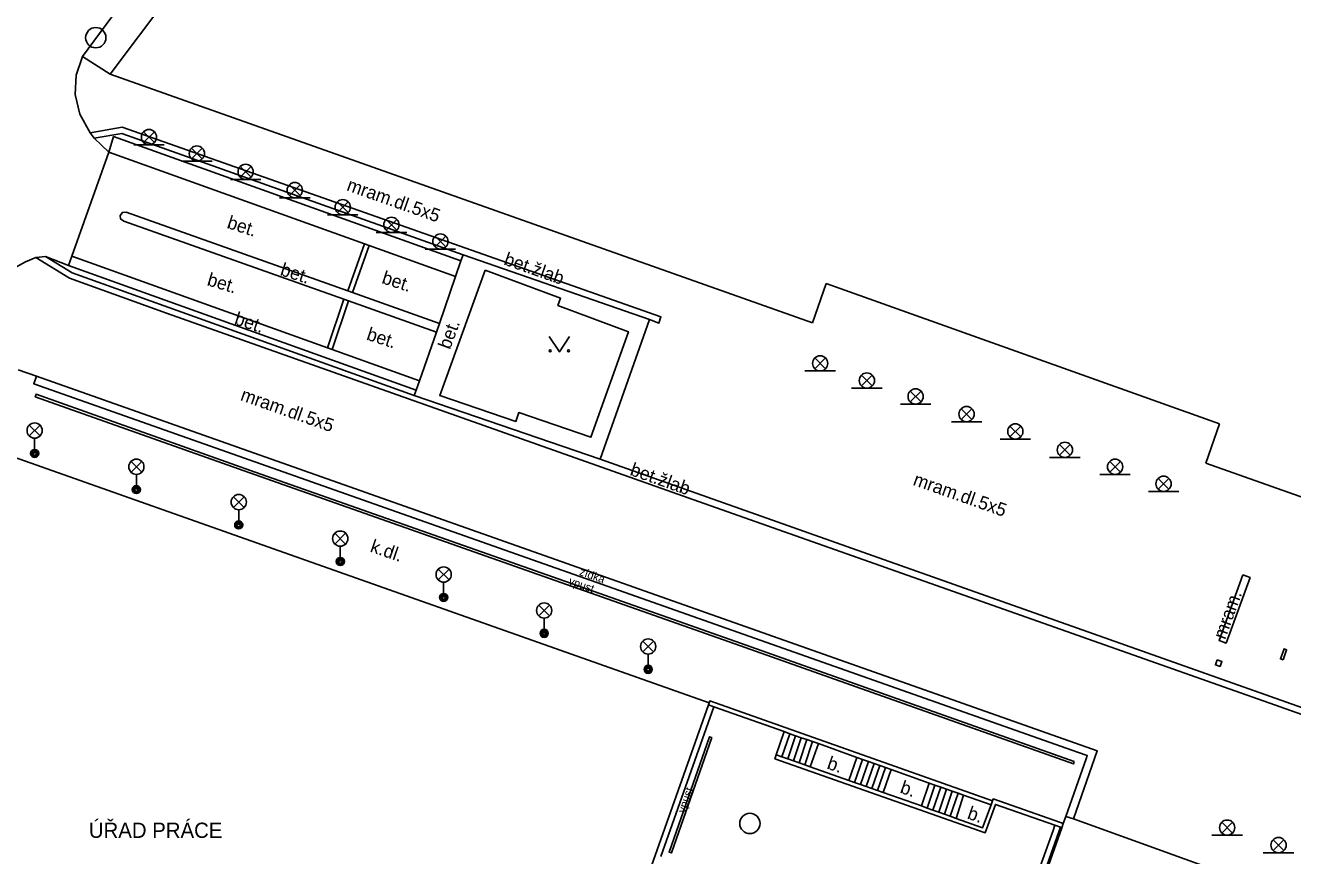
# Model space of a CAD drawing. Extents: x -598932 to -598196, y -1162207 to -1161504.
# Drawn here: x -598721.9 to -598659.5, y -1162142.2 to -1162101.4 of the extents above; entities that cross this region are included whole.
import ezdxf

# ---------------------------------------------------------------- set-up
doc = ezdxf.new("R2010")
doc.units = 0
for name, color, linetype in [('kanalizace - povrch.  znaky - skut. velikost', 7, 'Continuous'), ('Level 27', 7, 'Continuous'), ('Level 33', 7, 'Continuous'), ('Level 36', 7, 'Continuous'), ('TM - budovy zdene_ betonove - VP', 7, 'Continuous'), ('TM - chodniky - VP', 7, 'Continuous'), ('TM - horni hrana svahu', 7, 'Continuous'), ('TM - komunikace - VP', 7, 'Continuous'), ('TM - plot dreveny_ kovovy - VP', 7, 'Continuous'), ('TM - popis objektu', 7, 'Continuous'), ('TM - popis povrchu', 7, 'Continuous'), ('TM - poznamka', 7, 'Continuous'), ('TM - rozhrani ploch obecne - VP', 7, 'Continuous'), ('TM - schody - VP', 7, 'Continuous')]:
    doc.layers.add(name, color=color, linetype=linetype)

msp = doc.modelspace()

# ---------------------------------------------------------------- linework, layer by layer
at = {"layer": 'kanalizace - povrch.  znaky - skut. velikost'}
for points in [[(-598670.3, -1162137.6), (-598670.34, -1162137.72), (-598687.29, -1162131.71), (-598710.67, -1162123.47), (-598721.46, -1162119.64), (-598721.42, -1162119.52), (-598710.63, -1162123.35), (-598695.38, -1162128.72), (-598687.25, -1162131.59), (-598670.3, -1162137.6)], [(-598688.14, -1162136.42), (-598690.13, -1162142.1), (-598690.25, -1162142.06), (-598688.26, -1162136.38), (-598688.14, -1162136.42)]]:
    msp.add_lwpolyline(points, dxfattribs=at)
at = {"layer": 'Level 27'}
for centre in [(-598718.48, -1162101.96), (-598686.27, -1162140.65)]:
    msp.add_circle(centre, 0.5, dxfattribs=at)
at = {"layer": 'Level 33'}
for p, q in [((-598716.125, -1162107.12), (-598715.595, -1162106.59)), ((-598716.125, -1162106.59), (-598715.595, -1162107.12)), ((-598716.61, -1162107.23), (-598715.11, -1162107.23)), ((-598713.765, -1162107.93), (-598713.235, -1162107.4)), ((-598713.765, -1162107.4), (-598713.235, -1162107.93)), ((-598714.25, -1162108.04), (-598712.75, -1162108.04)), ((-598711.365, -1162108.83), (-598710.835, -1162108.3)), ((-598711.365, -1162108.3), (-598710.835, -1162108.83)), ((-598711.85, -1162108.94), (-598710.35, -1162108.94)), ((-598708.945, -1162109.73), (-598708.415, -1162109.2)), ((-598708.945, -1162109.2), (-598708.415, -1162109.73)), ((-598709.43, -1162109.84), (-598707.93, -1162109.84)), ((-598706.585, -1162110.57), (-598706.055, -1162110.04)), ((-598706.585, -1162110.04), (-598706.055, -1162110.57)), ((-598707.07, -1162110.68), (-598705.57, -1162110.68)), ((-598704.185, -1162111.44), (-598703.655, -1162110.91)), ((-598704.185, -1162110.91), (-598703.655, -1162111.44)), ((-598704.67, -1162111.55), (-598703.17, -1162111.55)), ((-598701.775, -1162112.26), (-598701.245, -1162111.73)), ((-598701.775, -1162111.73), (-598701.245, -1162112.26)), ((-598702.26, -1162112.37), (-598700.76, -1162112.37)), ((-598683.075, -1162118.26), (-598682.545, -1162117.73)), ((-598683.075, -1162117.73), (-598682.545, -1162118.26)), ((-598683.56, -1162118.37), (-598682.06, -1162118.37)), ((-598680.775, -1162119.11), (-598680.245, -1162118.58)), ((-598680.775, -1162118.58), (-598680.245, -1162119.11)), ((-598681.26, -1162119.22), (-598679.76, -1162119.22)), ((-598678.375, -1162119.89), (-598677.845, -1162119.36)), ((-598678.375, -1162119.36), (-598677.845, -1162119.89)), ((-598678.86, -1162120), (-598677.36, -1162120)), ((-598675.865, -1162120.76), (-598675.335, -1162120.23)), ((-598675.865, -1162120.23), (-598675.335, -1162120.76)), ((-598721.755, -1162121.57), (-598721.225, -1162121.04)), ((-598721.755, -1162121.04), (-598721.225, -1162121.57)), ((-598676.35, -1162120.87), (-598674.85, -1162120.87)), ((-598673.465, -1162121.61), (-598672.935, -1162121.08)), ((-598673.465, -1162121.08), (-598672.935, -1162121.61)), ((-598721.49, -1162121.68), (-598721.49, -1162122.43)), ((-598673.95, -1162121.72), (-598672.45, -1162121.72)), ((-598671.025, -1162122.52), (-598670.495, -1162121.99)), ((-598671.025, -1162121.99), (-598670.495, -1162122.52)), ((-598716.745, -1162123.35), (-598716.215, -1162122.82)), ((-598716.745, -1162122.82), (-598716.215, -1162123.35)), ((-598671.51, -1162122.63), (-598670.01, -1162122.63)), ((-598668.555, -1162123.35), (-598668.025, -1162122.82)), ((-598668.555, -1162122.82), (-598668.025, -1162123.35)), ((-598716.48, -1162123.46), (-598716.48, -1162124.21)), ((-598669.04, -1162123.46), (-598667.54, -1162123.46)), ((-598666.165, -1162124.19), (-598665.635, -1162123.66)), ((-598666.165, -1162123.66), (-598665.635, -1162124.19)), ((-598711.705, -1162125.09), (-598711.175, -1162124.56)), ((-598711.705, -1162124.56), (-598711.175, -1162125.09)), ((-598666.65, -1162124.3), (-598665.15, -1162124.3)), ((-598711.44, -1162125.2), (-598711.44, -1162125.95)), ((-598706.705, -1162126.89), (-598706.175, -1162126.36)), ((-598706.705, -1162126.36), (-598706.175, -1162126.89)), ((-598706.44, -1162127), (-598706.44, -1162127.75)), ((-598701.615, -1162128.66), (-598701.085, -1162128.13)), ((-598701.615, -1162128.13), (-598701.085, -1162128.66)), ((-598701.35, -1162128.77), (-598701.35, -1162129.52)), ((-598696.665, -1162130.43), (-598696.135, -1162129.9)), ((-598696.665, -1162129.9), (-598696.135, -1162130.43)), ((-598696.4, -1162130.54), (-598696.4, -1162131.29)), ((-598691.545, -1162132.2), (-598691.015, -1162131.67)), ((-598691.545, -1162131.67), (-598691.015, -1162132.2)), ((-598691.28, -1162132.31), (-598691.28, -1162133.06)), ((-598663.035, -1162141.12), (-598662.505, -1162140.59)), ((-598663.035, -1162140.59), (-598662.505, -1162141.12)), ((-598663.52, -1162141.23), (-598662.02, -1162141.23)), ((-598660.505, -1162141.98), (-598659.975, -1162141.45)), ((-598660.505, -1162141.45), (-598659.975, -1162141.98)), ((-598660.99, -1162142.09), (-598659.49, -1162142.09))]:
    msp.add_line(p, q, dxfattribs=at)
for centre, radius in [((-598715.86, -1162106.855), 0.375), ((-598713.5, -1162107.665), 0.375), ((-598711.1, -1162108.565), 0.375), ((-598708.68, -1162109.465), 0.375), ((-598706.32, -1162110.305), 0.375), ((-598703.92, -1162111.175), 0.375), ((-598701.51, -1162111.995), 0.375), ((-598682.81, -1162117.995), 0.375), ((-598680.51, -1162118.845), 0.375), ((-598678.11, -1162119.625), 0.375), ((-598675.6, -1162120.495), 0.375), ((-598721.49, -1162121.305), 0.375), ((-598673.2, -1162121.345), 0.375), ((-598721.49, -1162122.43), 0.2), ((-598721.49, -1162122.43), 0.145), ((-598721.49, -1162122.43), 0.0876), ((-598670.76, -1162122.255), 0.375), ((-598716.48, -1162123.085), 0.375), ((-598668.29, -1162123.085), 0.375), ((-598665.9, -1162123.925), 0.375), ((-598716.48, -1162124.21), 0.2), ((-598716.48, -1162124.21), 0.145), ((-598716.48, -1162124.21), 0.0876), ((-598711.44, -1162124.825), 0.375), ((-598711.44, -1162125.95), 0.2), ((-598711.44, -1162125.95), 0.145), ((-598711.44, -1162125.95), 0.0876), ((-598706.44, -1162126.625), 0.375), ((-598706.44, -1162127.75), 0.2), ((-598706.44, -1162127.75), 0.145), ((-598706.44, -1162127.75), 0.0876), ((-598701.35, -1162128.395), 0.375), ((-598701.35, -1162129.52), 0.2), ((-598701.35, -1162129.52), 0.145), ((-598701.35, -1162129.52), 0.0876), ((-598696.4, -1162130.165), 0.375), ((-598696.4, -1162131.29), 0.2), ((-598696.4, -1162131.29), 0.145), ((-598696.4, -1162131.29), 0.0876), ((-598691.28, -1162131.935), 0.375), ((-598691.28, -1162133.06), 0.2), ((-598691.28, -1162133.06), 0.145), ((-598691.28, -1162133.06), 0.0876), ((-598662.77, -1162140.855), 0.375), ((-598660.24, -1162141.715), 0.375)]:
    msp.add_circle(centre, radius, dxfattribs=at)
at = {"layer": 'Level 36'}
msp.add_lwpolyline([(-598696.15, -1162116.68), (-598695.65, -1162117.43), (-598695.15, -1162116.68)], dxfattribs=at)
for centre in [(-598696.1, -1162117.38), (-598695.201, -1162117.38)]:
    msp.add_circle(centre, 0.05, dxfattribs=at)
at = {"layer": 'TM - budovy zdene_ betonove - VP'}
for points in [[(-598710.79, -1162094.46), (-598717.77, -1162103.75)], [(-598717.77, -1162103.75), (-598683.19, -1162116)], [(-598683.19, -1162116), (-598682.51, -1162114.07)], [(-598682.51, -1162114.07), (-598663.14, -1162120.98)], [(-598663.14, -1162120.98), (-598663.82, -1162122.91)], [(-598688.27, -1162134.71), (-598724.7, -1162121.85)], [(-598663.82, -1162122.91), (-598634.85, -1162133.15)], [(-598728.07, -1162159.58), (-598700.55, -1162169.39), (-598688.31, -1162134.81)], [(-598670.71, -1162140.3), (-598670.84, -1162140.66)], [(-598670.34, -1162140.43), (-598670.71, -1162140.3)], [(-598642.61, -1162150.43), (-598670.34, -1162140.43)], [(-598670.91, -1162140.86), (-598682.79, -1162174.42)], [(-598670.84, -1162140.66), (-598670.91, -1162140.86)]]:
    msp.add_lwpolyline(points, dxfattribs=at)
at = {"layer": 'TM - chodniky - VP'}
for points in [[(-598722.3, -1162118.31), (-598721.4, -1162118.63)], [(-598721.4, -1162118.63), (-598669.17, -1162137.07), (-598670.34, -1162140.43)], [(-598660.02, -1162132.6), (-598660.15, -1162132.55), (-598659.97, -1162132.05), (-598659.84, -1162132.1), (-598660.02, -1162132.6)], [(-598663.27, -1162132.6), (-598663.03, -1162132.68), (-598663.12, -1162132.92), (-598663.35, -1162132.84), (-598663.27, -1162132.6)]]:
    msp.add_lwpolyline(points, dxfattribs=at)
at = {"layer": 'TM - horni hrana svahu'}
for points in [[(-598705.253, -1162112.11), (-598706.07, -1162114.43)], [(-598705.84, -1162114.51), (-598705.012, -1162112.196)], [(-598706.27, -1162114.84), (-598707.07, -1162117.23)], [(-598706.84, -1162117.31), (-598706.03, -1162114.92)]]:
    msp.add_lwpolyline(points, dxfattribs=at)
at = {"layer": 'TM - komunikace - VP'}
for points in [[(-598719.14, -1162102.89), (-598713.12, -1162094.74)], [(-598718.76, -1162106.64), (-598719.27, -1162105.73), (-598719.5, -1162104.75), (-598719.44, -1162103.8), (-598719.14, -1162102.89)], [(-598718.56, -1162106.91), (-598718.76, -1162106.64)], [(-598717.84, -1162107.6), (-598718.56, -1162106.91)], [(-598700.76, -1162113.72), (-598705.012, -1162112.196), (-598705.253, -1162112.11), (-598717.84, -1162107.6)], [(-598728.84, -1162119.71), (-598728.62, -1162119.43), (-598725.8, -1162115.62), (-598724.61, -1162114.53), (-598723.29, -1162113.73), (-598721.94, -1162112.99), (-598721.43, -1162112.79)], [(-598721.43, -1162112.79), (-598720.95, -1162112.73)], [(-598720.95, -1162112.73), (-598719.82, -1162113.18)], [(-598719.82, -1162113.18), (-598702.7, -1162119.32)], [(-598701.56, -1162116.03), (-598700.76, -1162113.72)], [(-598701.71, -1162116.46), (-598701.56, -1162116.03)], [(-598702.54, -1162118.85), (-598701.71, -1162116.46)], [(-598702.7, -1162119.32), (-598702.54, -1162118.85)], [(-598688.05, -1162134.9), (-598690.66, -1162142.27)], [(-598684.98, -1162137.27), (-598684.59, -1162136.13)], [(-598671.25, -1162140.73), (-598674.18, -1162139.71), (-598674.69, -1162141.11), (-598685.04, -1162137.46), (-598684.98, -1162137.27)], [(-598673.51, -1162147.01), (-598671.34, -1162140.99), (-598671.25, -1162140.73)]]:
    msp.add_lwpolyline(points, dxfattribs=at)
at = {"layer": 'TM - plot dreveny_ kovovy - VP'}
for points in [[(-598688.31, -1162134.81), (-598688.05, -1162134.9)], [(-598688.05, -1162134.9), (-598684.59, -1162136.13)]]:
    msp.add_lwpolyline(points, dxfattribs=at)
at = {"layer": 'TM - rozhrani ploch obecne - VP'}
for points in [[(-598719.14, -1162102.89), (-598717.77, -1162103.75)], [(-598718.76, -1162106.64), (-598717.18, -1162106.36), (-598690.65, -1162115.71), (-598690.75, -1162116.01), (-598691.21, -1162115.83)], [(-598700.39, -1162112.65), (-598717.19, -1162106.67), (-598718.56, -1162106.91)], [(-598717.84, -1162107.6), (-598717.6, -1162106.83), (-598700.5, -1162112.94)], [(-598717.84, -1162107.6), (-598719.66, -1162112.72)], [(-598706.27, -1162114.84), (-598717.1, -1162110.99), (-598717.26, -1162110.88), (-598717.28, -1162110.71), (-598717.17, -1162110.56), (-598716.98, -1162110.55), (-598706.07, -1162114.43)], [(-598721.43, -1162112.79), (-598719.78, -1162113.8), (-598714.99, -1162115.52), (-598689.31, -1162124.62), (-598650.44, -1162138.33), (-598639.68, -1162142.2)], [(-598720.95, -1162112.73), (-598719.65, -1162113.53), (-598702.8, -1162119.57)], [(-598719.66, -1162112.72), (-598719.82, -1162113.18)], [(-598719.66, -1162112.72), (-598707.07, -1162117.23)], [(-598700.76, -1162113.72), (-598700.5, -1162112.94)], [(-598700.5, -1162112.94), (-598700.39, -1162112.65)], [(-598691.21, -1162115.83), (-598700.39, -1162112.65)], [(-598699.3, -1162113.4), (-598695.59, -1162114.79), (-598695.72, -1162115.14), (-598692.25, -1162116.44), (-598694.1, -1162121.63), (-598697.65, -1162120.42), (-598697.79, -1162120.85), (-598701.54, -1162119.57), (-598699.3, -1162113.4)], [(-598706.03, -1162114.92), (-598706.27, -1162114.84)], [(-598706.07, -1162114.43), (-598705.84, -1162114.51), (-598701.56, -1162116.03)], [(-598701.71, -1162116.46), (-598706.03, -1162114.92)], [(-598691.21, -1162115.83), (-598693.65, -1162122.72)], [(-598707.07, -1162117.23), (-598706.84, -1162117.31), (-598702.54, -1162118.85)], [(-598670.71, -1162140.3), (-598669.72, -1162137.47), (-598669.66, -1162137.31), (-598670.09, -1162137.16), (-598721.53, -1162119), (-598721.4, -1162118.63)], [(-598702.7, -1162119.32), (-598702.8, -1162119.57)], [(-598702.8, -1162119.57), (-598693.65, -1162122.72)], [(-598693.65, -1162122.72), (-598650.35, -1162138.05)], [(-598661.99, -1162128.41), (-598661.64, -1162128.54), (-598662.82, -1162131.77), (-598663.17, -1162131.64), (-598661.99, -1162128.41)], [(-598688.31, -1162134.81), (-598688.27, -1162134.71)], [(-598688.27, -1162134.71), (-598688.24, -1162134.62), (-598674.33, -1162139.54)], [(-598684.3, -1162136.23), (-598684.59, -1162136.13)], [(-598684.02, -1162136.33), (-598684.3, -1162136.23)], [(-598683.74, -1162136.43), (-598684.02, -1162136.33)], [(-598683.46, -1162136.52), (-598683.74, -1162136.43)], [(-598683.18, -1162136.62), (-598683.46, -1162136.52)], [(-598682.89, -1162136.72), (-598683.3, -1162137.86)], [(-598682.89, -1162136.72), (-598683.18, -1162136.62)], [(-598681, -1162137.4), (-598682.89, -1162136.72)], [(-598684.69, -1162137.37), (-598684.98, -1162137.27)], [(-598684.41, -1162137.47), (-598684.69, -1162137.37)], [(-598684.13, -1162137.57), (-598684.41, -1162137.47)], [(-598683.85, -1162137.67), (-598684.13, -1162137.57)], [(-598683.57, -1162137.77), (-598683.85, -1162137.67)], [(-598683.3, -1162137.86), (-598683.57, -1162137.77)], [(-598681.4, -1162138.53), (-598683.3, -1162137.86)], [(-598681, -1162137.4), (-598681.4, -1162138.53)], [(-598680.72, -1162137.5), (-598681, -1162137.4)], [(-598680.43, -1162137.6), (-598680.72, -1162137.5)], [(-598680.15, -1162137.7), (-598680.43, -1162137.6)], [(-598679.87, -1162137.8), (-598680.15, -1162137.7)], [(-598679.59, -1162137.89), (-598679.87, -1162137.8)], [(-598679.31, -1162137.99), (-598679.59, -1162137.89)], [(-598681.12, -1162138.63), (-598681.4, -1162138.53)], [(-598679.31, -1162137.99), (-598679.71, -1162139.13)], [(-598677.44, -1162138.66), (-598679.31, -1162137.99)], [(-598680.83, -1162138.73), (-598681.12, -1162138.63)], [(-598680.55, -1162138.83), (-598680.83, -1162138.73)], [(-598680.27, -1162138.93), (-598680.55, -1162138.83)], [(-598679.99, -1162139.03), (-598680.27, -1162138.93)], [(-598679.71, -1162139.13), (-598679.99, -1162139.03)], [(-598677.82, -1162139.79), (-598679.71, -1162139.13)], [(-598677.44, -1162138.66), (-598677.82, -1162139.79)], [(-598677.16, -1162138.76), (-598677.44, -1162138.66)], [(-598676.87, -1162138.86), (-598677.16, -1162138.76)], [(-598676.59, -1162138.96), (-598676.87, -1162138.86)], [(-598676.31, -1162139.06), (-598676.59, -1162138.96)], [(-598676.02, -1162139.16), (-598676.31, -1162139.06)], [(-598675.75, -1162139.25), (-598676.02, -1162139.16)], [(-598677.54, -1162139.89), (-598677.82, -1162139.79)], [(-598675.75, -1162139.25), (-598676.12, -1162140.4)], [(-598674.39, -1162139.73), (-598674.81, -1162140.86), (-598676.12, -1162140.4)], [(-598674.39, -1162139.73), (-598675.75, -1162139.25)], [(-598674.33, -1162139.54), (-598674.39, -1162139.73)], [(-598670.84, -1162140.66), (-598670.98, -1162140.61), (-598674.29, -1162139.44), (-598674.33, -1162139.54)], [(-598677.26, -1162139.99), (-598677.54, -1162139.89)], [(-598676.97, -1162140.09), (-598677.26, -1162139.99)], [(-598676.69, -1162140.19), (-598676.97, -1162140.09)], [(-598676.41, -1162140.29), (-598676.69, -1162140.19)], [(-598676.12, -1162140.4), (-598676.41, -1162140.29)], [(-598673.2, -1162147.09), (-598670.98, -1162140.83)], [(-598670.98, -1162140.83), (-598671.25, -1162140.73)], [(-598670.98, -1162140.83), (-598670.91, -1162140.86)]]:
    msp.add_lwpolyline(points, dxfattribs=at)
at = {"layer": 'TM - schody - VP'}
for points in [[(-598684.3, -1162136.23), (-598684.69, -1162137.37)], [(-598684.02, -1162136.33), (-598684.41, -1162137.47)], [(-598683.74, -1162136.43), (-598684.13, -1162137.57)], [(-598683.46, -1162136.52), (-598683.85, -1162137.67)], [(-598683.18, -1162136.62), (-598683.57, -1162137.77)], [(-598680.72, -1162137.5), (-598681.12, -1162138.63)], [(-598680.43, -1162137.6), (-598680.83, -1162138.73)], [(-598680.15, -1162137.7), (-598680.55, -1162138.83)], [(-598679.87, -1162137.8), (-598680.27, -1162138.93)], [(-598679.59, -1162137.89), (-598679.99, -1162139.03)], [(-598677.16, -1162138.76), (-598677.54, -1162139.89)], [(-598676.87, -1162138.86), (-598677.26, -1162139.99)], [(-598676.59, -1162138.96), (-598676.97, -1162140.09)], [(-598676.31, -1162139.06), (-598676.69, -1162140.19)], [(-598676.02, -1162139.16), (-598676.41, -1162140.29)]]:
    msp.add_lwpolyline(points, dxfattribs=at)

# ---------------------------------------------------------------- texts
at = {"layer": 'TM - popis objektu'}
msp.add_text('ÚŘAD PRÁCE', height=0.75, dxfattribs=at).set_placement((-598718.82, -1162141.36))
at = {"layer": 'TM - popis povrchu'}
for s, rotation, p in [('mram.dl.5x5', 340.55, (-598706.17, -1162109.47)), ('bet.', 342, (-598712.06, -1162111.32)), ('bet.', 342, (-598709.44, -1162113.64)), ('bet.', 343.28, (-598713.04, -1162114.14)), ('bet.', 342, (-598704.44, -1162114.04)), ('bet.', 342, (-598711.7, -1162116.06)), ('bet.', 69.6, (-598701.04, -1162117.35)), ('bet.', 342, (-598705.19, -1162116.82)), ('mram.dl.5x5', 340.55, (-598711.4, -1162119.8)), ('mram.dl.5x5', 340.55, (-598678.28, -1162123.97)), ('k.dl.', 341, (-598705.01, -1162127.26)), ('mram.', 70, (-598662.87, -1162131.63)), ('b.', 341, (-598682.52, -1162137.94)), ('b.', 341, (-598678.92, -1162139.13)), ('b.', 341, (-598675.61, -1162140.4))]:
    msp.add_text(s, height=0.65, rotation=rotation, dxfattribs=at).set_placement(p)
at = {"layer": 'TM - poznamka'}
for s, height, rotation, p in [('bet.žlab', 0.65, 340.55, (-598698.43, -1162113.12)), ('bet.žlab', 0.65, 340.5, (-598692.22, -1162123.48)), ('vpust', 0.4, 340.55628, (-598695.23, -1162128.87)), ('zídka', 0.4, 340.55628, (-598694.7, -1162128.41)), ('vpust', 0.4, 71, (-598689.47, -1162140.17))]:
    msp.add_text(s, height=height, rotation=rotation, dxfattribs=at).set_placement(p)

doc.saveas('drawing.dxf')
